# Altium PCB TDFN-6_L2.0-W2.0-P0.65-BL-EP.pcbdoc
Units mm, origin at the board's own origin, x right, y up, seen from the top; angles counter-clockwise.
Board outline 14.85 x 15.74 mm, 2 copper layers (Top Layer, Bottom Layer), stack 0 mm thick; 1 components, 0 nets, 7 pads, 0 vias.
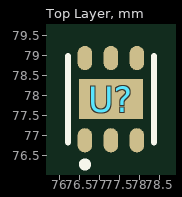
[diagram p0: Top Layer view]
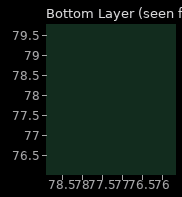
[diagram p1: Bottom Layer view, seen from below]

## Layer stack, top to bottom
Top Layer: signal copper (thickness not stored)
Bottom Layer: signal copper (thickness not stored)

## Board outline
84.702,69.85 69.85,69.85 69.85,85.589 84.702,85.589

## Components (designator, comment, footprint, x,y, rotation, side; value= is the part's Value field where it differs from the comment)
U? "" TDFN-6_L2.0-W2.0-P0.65-BL-EP 77.276,77.907 r0 top

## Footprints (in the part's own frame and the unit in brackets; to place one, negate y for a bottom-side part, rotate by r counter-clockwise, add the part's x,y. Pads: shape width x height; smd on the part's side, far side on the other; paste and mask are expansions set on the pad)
TDFN-6_L2.0-W2.0-P0.65-BL-EP [mm]
  oval 0.364x0.607 smd: 1(-0.65,-1.028) 2(0,-1.028) 3(0.65,-1.028) 4(0.65,1.028) 5(0,1.028) 6(-0.65,1.028)
  rect 1.6x1 smd: 7(0,0)
  silkscreen extent -1.08,-1.71 1.08,1.08

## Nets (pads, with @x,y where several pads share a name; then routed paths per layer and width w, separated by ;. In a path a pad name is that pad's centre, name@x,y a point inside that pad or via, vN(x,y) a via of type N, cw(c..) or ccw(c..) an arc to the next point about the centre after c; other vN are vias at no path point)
pads on no net: U?.1 U?.2 U?.3 U?.4 U?.5 U?.6 U?.7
